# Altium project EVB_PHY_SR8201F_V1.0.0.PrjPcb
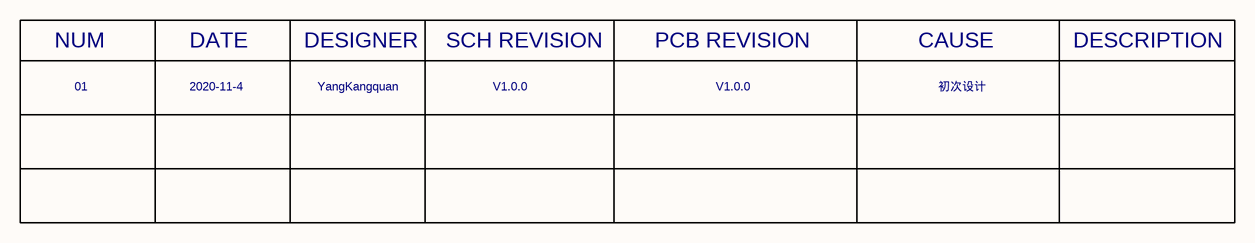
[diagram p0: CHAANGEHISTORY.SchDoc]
3 sheets, 55 parts. Net scope: flat (ports and power ports of the same name join across sheets).
Board file: EVB_PHY_SR8201F_V1.0.0.PcbDoc
Sheets:
  CHAANGEHISTORY.SchDoc
  SR8201F.SchDoc
  INTERFACE.SchDoc

## Sheet CHAANGEHISTORY.SchDoc: EVB_PHY_SR8201F_V1.0.0
size A4; Revision: V1.0.0; SheetNumber: 1; SheetTotal: 3

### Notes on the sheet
- NUM
- DATE
- DESIGNER
- SCH REVISION
- PCB REVISION
- CAUSE
- DESCRIPTION
- 01
- 2020-11-4
- YangKangquan
- V1.0.0
- 初次设计

## Sheet SR8201F.SchDoc: EVB_PHY_SR8201F_V1.0.0
size A4; Revision: V1.0.0; SheetNumber: 2; SheetTotal: 3
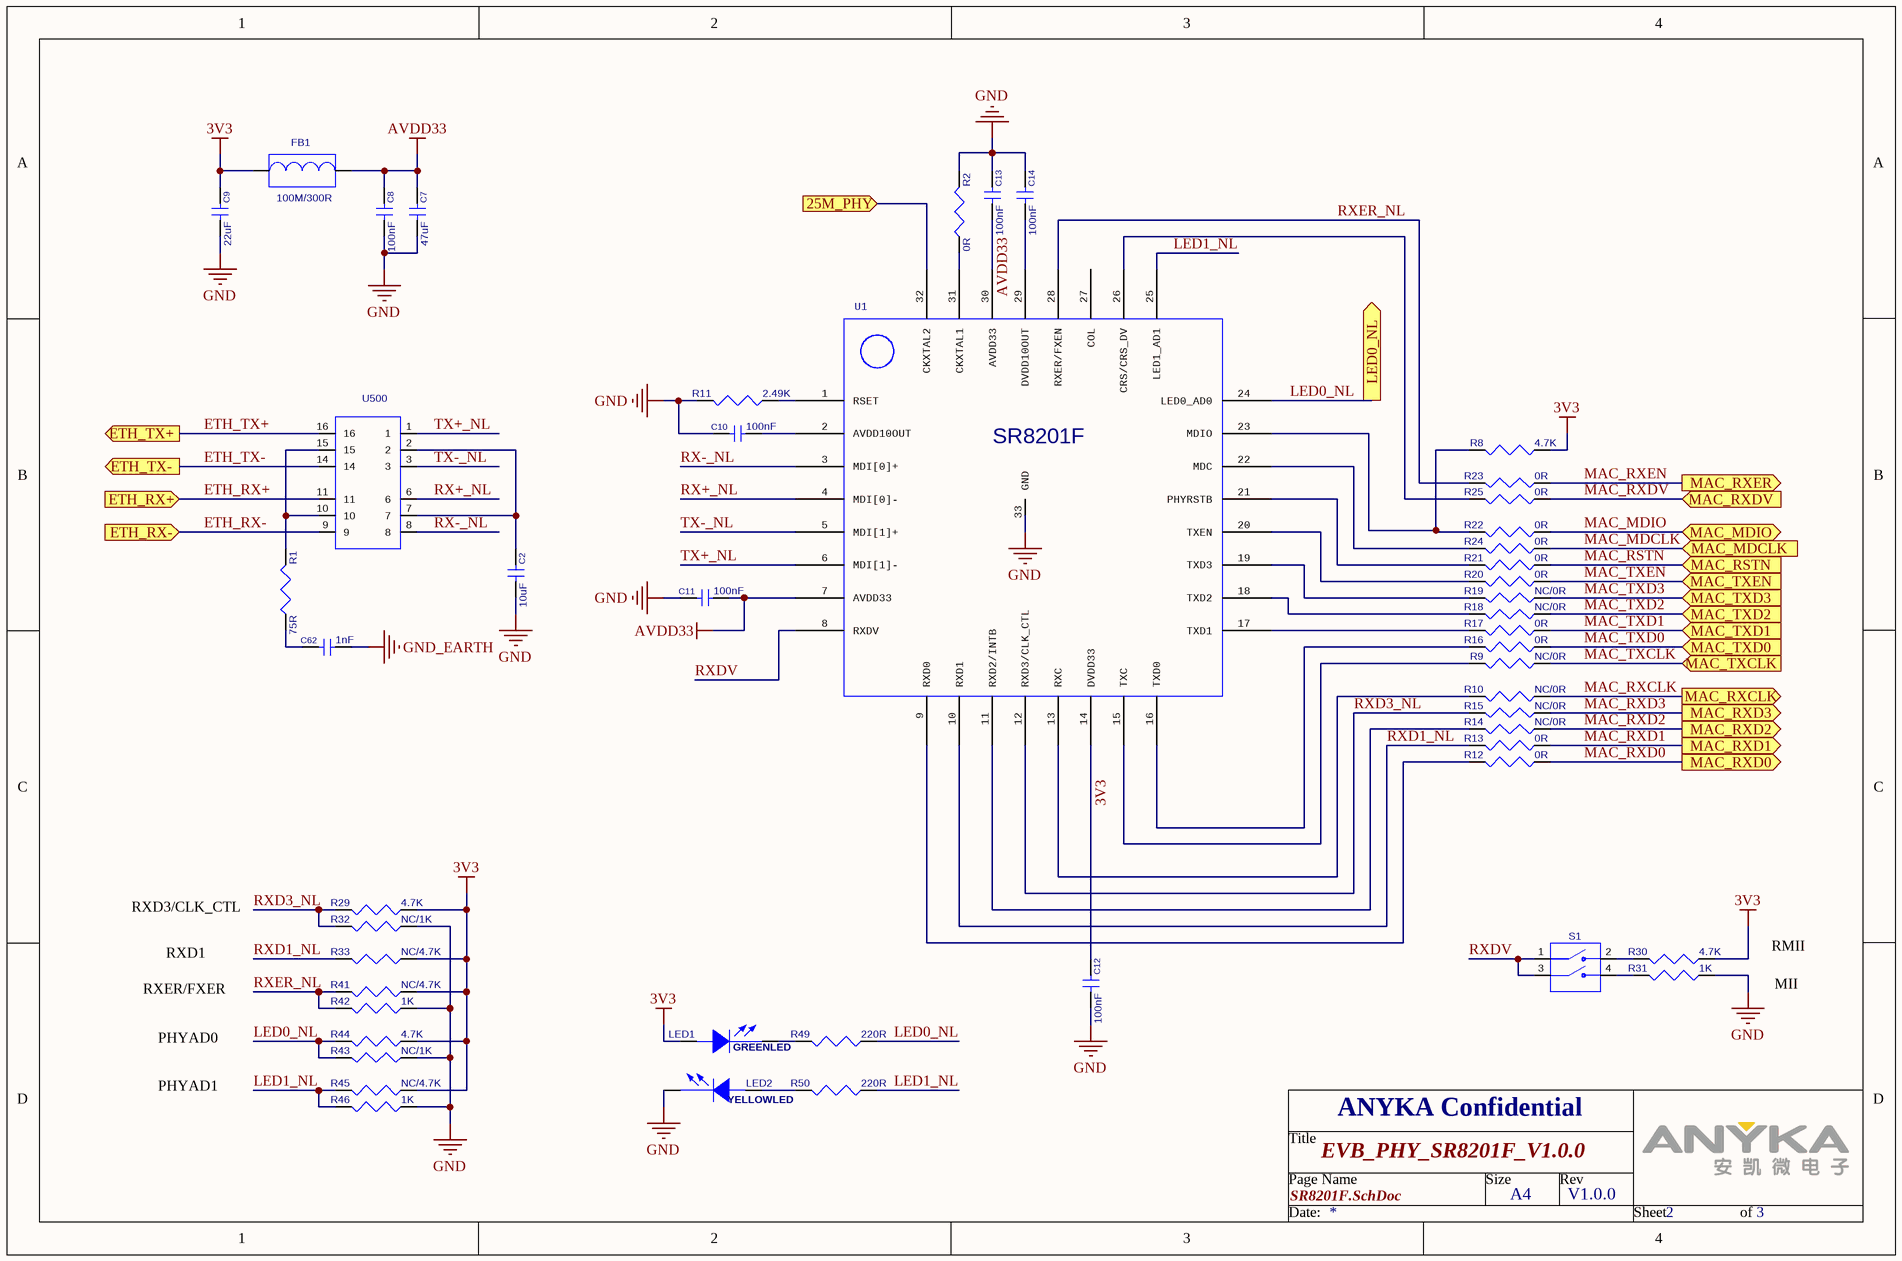
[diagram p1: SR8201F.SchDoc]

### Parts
C2  10uF  [C0805]
C7  47uF  [C1210]
C8  100nF  [C0603]
C9  22uF  [C1210]
C10  100nF  [C0603]
C11  100nF  [C0603]
C12  100nF  [C0603]
C13  100nF  [C0603]
C14  100nF  [C0603]
C62  1nF  [C1206]
FB1  100M/300R  [FB0603]
LED1  GREENLED  [LED0603]
LED2  YELLOWLED  [LED0603]
R1  75R  [R0603]
R2  0R  [R0603]
R8  4.7K  [R0603]
R9  NC/0R  [R0603]
R10  NC/0R  [R0603]
R11  2.49K  [R0603]
R12  0R  [R0603]
R13  0R  [R0603]
R14  NC/0R  [R0603]
R15  NC/0R  [R0603]
R16  0R  [R0603]
R17  0R  [R0603]
R18  NC/0R  [R0603]
R19  NC/0R  [R0603]
R20  0R  [R0603]
R21  0R  [R0603]
R22  0R  [R0603]
R23  0R  [R0603]
R24  0R  [R0603]
R25  0R  [R0603]
R29  4.7K  [R0603]
R30  4.7K  [R0603]
R31  1K  [R0603]
R32  NC/1K  [R0603]
R33  NC/4.7K  [R0603]
R41  NC/4.7K  [R0603]
R42  1K  [R0603]
R43  NC/1K  [R0603]
R44  4.7K  [R0603]
R45  NC/4.7K  [R0603]
R46  1K  [R0603]
R49  220R  [R0603]
R50  220R  [R0603]
S1  SWITCH_DHM-02  [SWITCH_DHM-02_1MM27_5MM6X8MM3]  (value not drawn)
U1  SR8201F  [QFN32_0MM5_5X5MM]  (value not drawn)
U500  TRC1102NLE  [TRC1102NLE]  (value not drawn)

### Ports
25M_PHY (in), ETH_RX+ (in), ETH_RX- (in), ETH_TX+ (out), ETH_TX- (out), LED0_NL (out), MAC_MDCLK (in), MAC_MDIO (bidir), MAC_RSTN (in), MAC_RXCLK (out), MAC_RXD0 (out), MAC_RXD1 (out), MAC_RXD2 (out), MAC_RXD3 (out), MAC_RXDV (in), MAC_RXER (out), MAC_TXCLK (in), MAC_TXD0 (in), MAC_TXD1 (in), MAC_TXD2 (in), MAC_TXD3 (in), MAC_TXEN (in)

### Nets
3V3: C9.1 C12.1 FB1.1 LED1.A R8.1 R29.1 R30.1 R33.1 R41.1 R44.1 R45.1 U1.14(DVDD33)
AVDD33: C7.1 C8.1 C11.2 C13.2 FB1.2 U1.7(AVDD33) U1.30(AVDD33)
GND: C2.2 C7.2 C8.2 C9.2 C10.1 C11.1 C12.2 C13.1 C14.1 LED2.K R2.2 R11.2 R31.1 R32.1 R42.1 R43.1 R46.1 U1.33(GND)
GND_EARTH: C62.2
ETH_RX+: U500.11 ; port ETH_RX+
ETH_RX-: U500.9 ; port ETH_RX-
ETH_TX+: U500.16 ; port ETH_TX+
ETH_TX-: U500.14 ; port ETH_TX-
LED0_NL: R43.2 R44.2 R49.1 U1.24(LED0_AD0) ; port LED0_NL
LED1_NL: R45.2 R46.2 R50.1 U1.25(LED1_AD1)
MAC_MDCLK: R24.1 ; port MAC_MDCLK
MAC_MDIO: R22.1 ; port MAC_MDIO
MAC_RSTN: R21.1 ; port MAC_RSTN
MAC_RXCLK: R10.1 ; port MAC_RXCLK
MAC_RXD0: R12.1 ; port MAC_RXD0
MAC_RXD1: R13.1 ; port MAC_RXD1
MAC_RXD2: R14.1 ; port MAC_RXD2
MAC_RXD3: R15.1 ; port MAC_RXD3
MAC_RXDV: R25.1 ; port MAC_RXDV
MAC_RXEN: R23.1 ; port MAC_RXER
MAC_TXCLK: R9.1 ; port MAC_TXCLK
MAC_TXD0: R16.1 ; port MAC_TXD0
MAC_TXD1: R17.1 ; port MAC_TXD1
MAC_TXD2: R18.1 ; port MAC_TXD2
MAC_TXD3: R19.1 ; port MAC_TXD3
MAC_TXEN: R20.1 ; port MAC_TXEN
RX+_NL: U1.4(MDI[0]-) U500.6
RX-_NL: U1.3(MDI[0]+) U500.8
RXD1_NL: R13.2 R33.2 U1.10(RXD1)
RXD3_NL: R15.2 R29.2 R32.2 U1.12(RXD3/CLK_CTL)
RXDV: S1.1 S1.3 U1.8(RXDV)
RXER_NL: R23.2 R41.2 R42.2 U1.28(RXER/FXEN)
TX+_NL: U1.6(MDI[1]-) U500.1
TX-_NL: U1.5(MDI[1]+) U500.3
NetC2_1: C2.1 U500.2 U500.7
NetC10_2: C10.2 U1.2(AVDD10OUT)
NetC14_2: C14.2 U1.29(DVDD10OUT)
NetC62_1: C62.1 R1.1
NetCON1_7: U1.32(CKXTAL2) ; port 25M_PHY
NetLED1_K: LED1.K R49.2
NetLED2_A: LED2.A R50.2
NetR1_2: R1.2 U500.10 U500.15
NetR2_1: R2.1 U1.31(CKXTAL1)
NetR8_2: R8.2 R22.2 U1.23(MDIO)
NetR9_2: R9.2 U1.15(TXC)
NetR10_2: R10.2 U1.13(RXC)
NetR11_1: R11.1 U1.1(RSET)
NetR12_2: R12.2 U1.9(RXD0)
NetR14_2: R14.2 U1.11(RXD2/INTB)
NetR16_2: R16.2 U1.16(TXD0)
NetR17_2: R17.2 U1.17(TXD1)
NetR18_2: R18.2 U1.18(TXD2)
NetR19_2: R19.2 U1.19(TXD3)
NetR20_2: R20.2 U1.20(TXEN)
NetR21_2: R21.2 U1.21(PHYRSTB)
NetR24_2: R24.2 U1.22(MDC)
NetR25_2: R25.2 U1.26(CRS/CRS_DV)
NetR30_2: R30.2 S1.2
NetR31_2: R31.2 S1.4

Not connected (* = marked no-connect by the designer): U1 27(COL)

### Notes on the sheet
- RXD3/CLK_CTL
- RXD1
- RMII
- RXER/FXER
- MII
- PHYAD0
- PHYAD1

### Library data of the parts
C2 = CC0501063XX: C/C,10uF,16V,+/-20%,0805; Catalog: 陶瓷电容
C7 = CC1004760XX: C/C,47uF,10V,+/-10%,1210; Catalog: 陶瓷电容
C8 C10-C14 = CC0301040XX: C/C,100nF,25V,+/-5%,0603; Catalog: 陶瓷电容
C9 = CC1002260XX: C/C,22uF,16V,+/-10%,1210; Catalog: 陶瓷电容
C62 = CC0601021XX: C/C,1nF,2KV,+/-10%,1206; Catalog: 陶瓷电容
FB1 = BE0303011XX: BEAD,300R,100MHz,0603; SOURCE_PATH: D:\PROGRAM FILES\ORCAD\ORCAD_10.5\TOOLS\CAPTURE\LIBRARY\DISCRETE.OLB; Catalog: 贴片磁珠
LED1 = LE03GXX00XX: GREENLED,0603; Catalog: 二极管
LED2 = LE03YXX00XX: YELLOW,LED0603; Catalog: 二极管
R1 = CR0375R00XX: Res,75R,1/10W,+/-1%,0603; Catalog: 贴片电阻
R2 R12 R13 R16 R17 R20-R25 = CR0300000XX: Res,0R,1/10W,+/-5%,0603; Catalog: 贴片电阻
R8 R29 R30 R44 = CR0304720XX: Res,4.7K,1/10W,+/-5%,0603; Catalog: 贴片电阻
R9 R10 R14 R15 R18 R19 = CR0300000XX: Res,0R,1/10W,+/-5%,0603; Remark: NC; Catalog: 贴片电阻
R11 = CR0324910XX: Res,2.49K,1/10W,+/-1%,0603; Catalog: 贴片电阻
R31 R42 R46 = CR0301020XX: Res,1K,1/10W,+/-5%,0603; Catalog: 贴片电阻
R32 R43 = CR0301020XX: Res,1K,1/10W,+/-5%,0603; Remark: NC; Catalog: 贴片电阻
R33 R41 R45 = CR0304720XX: Res,4.7K,1/10W,+/-5%,0603; Remark: NC; Catalog: 贴片电阻
R49 R50 = CR0302211XX: Res,220R,1/10W,+/-1%,0603; Catalog: 贴片电阻
S1 = SWSL04000XX: 开关,SlideSwitch,yimen,DHM-02,24V,1.27pitch,4pin; Catalog: Switch
U1 = JCQFNDR00XX: PHY芯片,SR8201F_KY，封装QFN32; Catalog: 集成电路
U500 = TFSMD1601XX: Transformer,Trxcom,TRC1188NL,16pin; Part_RNEfNErNEncNE: NU704; room: ethernet; NC: 4,5,12,13; Source_Path: D:\MOBILE_PROJECT\WINCE\WINCE-7802\LIBRARY1.OLB; Catalog: 网络变压器

## Sheet INTERFACE.SchDoc: EVB_PHY_SR8201F_V1.0.0
size A4; Revision: V1.0.0; SheetNumber: 3; SheetTotal: 3
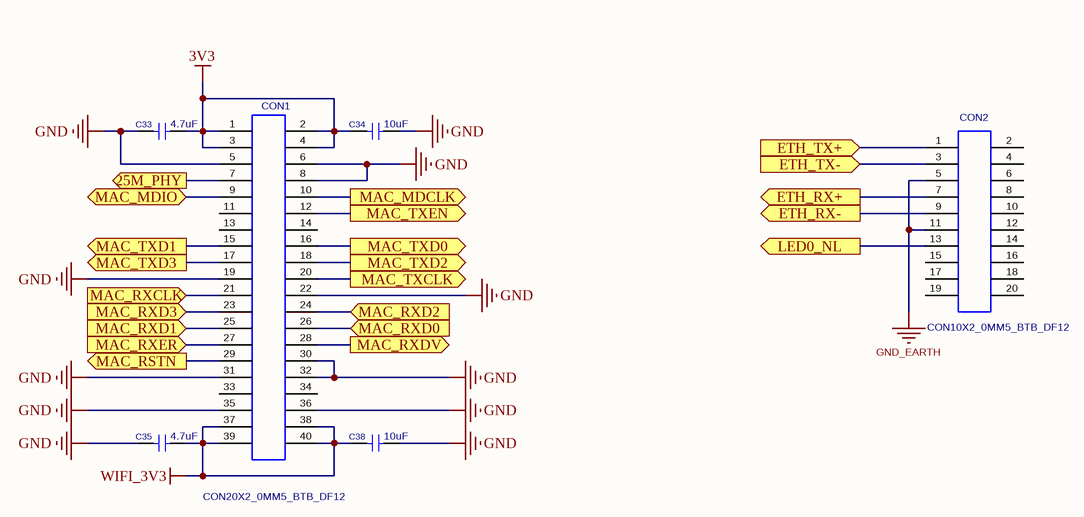
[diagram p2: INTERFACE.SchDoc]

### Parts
C33  4.7uF  [C0603]
C34  10uF  [C0805]
C35  4.7uF  [C0603]
C38  10uF  [C0805]
CON1  CON20X2_0MM5_BTB_DF12  [CON20X2_0MM5_BTB_DF12_N]
CON2  CON10X2_0MM5_BTB_DF12  [CON10X2_0MM5_BTB_DF12_N]

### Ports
25M_PHY (out), ETH_RX+ (out), ETH_RX- (out), ETH_TX+ (in), ETH_TX- (in), LED0_NL (out), MAC_MDCLK (out), MAC_MDIO (bidir), MAC_RSTN (out), MAC_RXCLK (in), MAC_RXD0 (in), MAC_RXD1 (in), MAC_RXD2 (in), MAC_RXD3 (in), MAC_RXDV (out), MAC_RXER (in), MAC_TXCLK (out), MAC_TXD0 (out), MAC_TXD1 (out), MAC_TXD2 (out), MAC_TXD3 (out), MAC_TXEN (out)

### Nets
3V3: C33.2 C34.1 CON1.1 CON1.2 CON1.3 CON1.4
GND: C33.1 C34.2 C35.1 C38.2 CON1.5 CON1.6 CON1.8 CON1.19 CON1.22 CON1.30 CON1.31 CON1.32 CON1.35 CON1.36
GND_EARTH: CON2.5 CON2.11
WIFI_3V3: C35.2 C38.1 CON1.37 CON1.38 CON1.39 CON1.40
ETH_RX+: CON2.7 ; port ETH_RX+
ETH_RX-: CON2.9 ; port ETH_RX-
ETH_TX+: CON2.1 ; port ETH_TX+
ETH_TX-: CON2.3 ; port ETH_TX-
LED0_NL: CON2.13 ; port LED0_NL
MAC_MDCLK: CON1.10 ; port MAC_MDCLK
MAC_MDIO: CON1.9 ; port MAC_MDIO
MAC_RSTN: CON1.29 ; port MAC_RSTN
MAC_RXCLK: CON1.21 ; port MAC_RXCLK
MAC_RXD0: CON1.26 ; port MAC_RXD0
MAC_RXD1: CON1.25 ; port MAC_RXD1
MAC_RXD2: CON1.24 ; port MAC_RXD2
MAC_RXD3: CON1.23 ; port MAC_RXD3
MAC_RXDV: CON1.28 ; port MAC_RXDV
MAC_RXEN: CON1.27 ; port MAC_RXER
MAC_TXCLK: CON1.20 ; port MAC_TXCLK
MAC_TXD0: CON1.16 ; port MAC_TXD0
MAC_TXD1: CON1.15 ; port MAC_TXD1
MAC_TXD2: CON1.18 ; port MAC_TXD2
MAC_TXD3: CON1.17 ; port MAC_TXD3
MAC_TXEN: CON1.12 ; port MAC_TXEN
NetCON1_7: CON1.7 ; port 25M_PHY

Not connected (* = marked no-connect by the designer): CON1 11 13 14 33 34; CON2 2 4 6 8 10 12 14 15 16 17 18 19 20

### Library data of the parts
C33 C35 = CC0304751XX: C/C,4.7uF,16V,+/-10%,0603; Catalog: 陶瓷电容
C34 C38 = CC0501063XX: C/C,10uF,16V,+/-20%,0805; Catalog: 陶瓷电容
CON1 = CNBBM4000XX: 0.5mm ，BTB2*20Pin，SMT，公座，H3.0，DF12#(3.0)-40DS-0.5; PCB DECAL: CON20X2_0MM5_BTB_DF12_BOTTOM; Catalog: Connector
CON2 = CNBBM2000XX: 0.5mm ，BTB2*10Pin，SMT，公座，H3.0，DF12#(3.0)-20DS-0.5; PCB DECAL: CON10X2_0MM5_BTB_DF12_BOTTOM; Catalog: Connector

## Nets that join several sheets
3V3: SR8201F (12 pins), INTERFACE (6 pins)
GND: SR8201F (18 pins), INTERFACE (14 pins)
GND_EARTH: SR8201F (C62.2), INTERFACE (CON2.5 CON2.11)
ETH_RX+: SR8201F (U500.11), INTERFACE (CON2.7)
ETH_RX-: SR8201F (U500.9), INTERFACE (CON2.9)
ETH_TX+: SR8201F (U500.16), INTERFACE (CON2.1)
ETH_TX-: SR8201F (U500.14), INTERFACE (CON2.3)
LED0_NL: SR8201F (R43.2 R44.2 R49.1 U1.24), INTERFACE (CON2.13)
MAC_MDCLK: SR8201F (R24.1), INTERFACE (CON1.10)
MAC_MDIO: SR8201F (R22.1), INTERFACE (CON1.9)
MAC_RSTN: SR8201F (R21.1), INTERFACE (CON1.29)
MAC_RXCLK: SR8201F (R10.1), INTERFACE (CON1.21)
MAC_RXD0: SR8201F (R12.1), INTERFACE (CON1.26)
MAC_RXD1: SR8201F (R13.1), INTERFACE (CON1.25)
MAC_RXD2: SR8201F (R14.1), INTERFACE (CON1.24)
MAC_RXD3: SR8201F (R15.1), INTERFACE (CON1.23)
MAC_RXDV: SR8201F (R25.1), INTERFACE (CON1.28)
MAC_RXEN: SR8201F (R23.1), INTERFACE (CON1.27)
MAC_TXCLK: SR8201F (R9.1), INTERFACE (CON1.20)
MAC_TXD0: SR8201F (R16.1), INTERFACE (CON1.16)
MAC_TXD1: SR8201F (R17.1), INTERFACE (CON1.15)
MAC_TXD2: SR8201F (R18.1), INTERFACE (CON1.18)
MAC_TXD3: SR8201F (R19.1), INTERFACE (CON1.17)
MAC_TXEN: SR8201F (R20.1), INTERFACE (CON1.12)
NetCON1_7: SR8201F (U1.32), INTERFACE (CON1.7)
